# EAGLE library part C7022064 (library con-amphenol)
AMPHENOL CONNECTOR
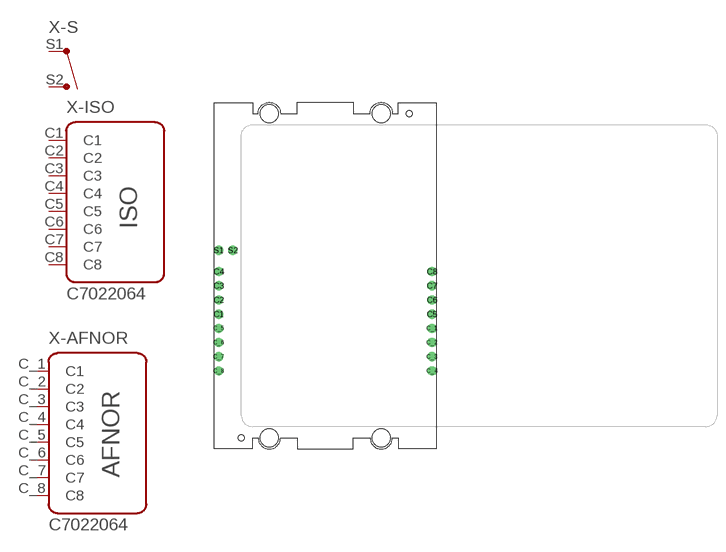
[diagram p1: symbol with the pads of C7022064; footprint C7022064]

Designator prefix X; gates -S=S -ISO=ISO8 -AFNOR=AFNOR

## C7022064 (OC_FARNELL: unknown; OC_NEWARK: unknown)  [C7022064]
C1  -ISO:C1  pas
C2  -ISO:C2  pas
C3  -ISO:C3  pas
C4  -ISO:C4  pas
C5  -ISO:C5  pas
C6  -ISO:C6  pas
C7  -ISO:C7  pas
C8  -ISO:C8  pas
C_1  -AFNOR:C1  pas
C_2  -AFNOR:C2  pas
C_3  -AFNOR:C3  pas
C_4  -AFNOR:C4  pas
C_5  -AFNOR:C5  pas
C_6  -AFNOR:C6  pas
C_7  -AFNOR:C7  pas
C_8  -AFNOR:C8  pas
S1  -S:S1  pas
S2  -S:S2  pas

## Footprint C7022064 (pad centres in mm)
AMPHENOL CONNECTOR
drill 1.1 round: C1 -19.05,-6.88; C2 -19.05,-4.34; C3 -19.05,-1.8; C4 -19.05,0.74; C5 19.05,-6.88; C6 19.05,-4.34; C7 19.05,-1.8; C8 19.05,0.74; C_1 19.05,-9.42; C_2 19.05,-11.96; C_3 19.05,-14.5; C_4 19.05,-17.04; C_5 -19.05,-9.42; C_6 -19.05,-11.96; C_7 -19.05,-14.5; C_8 -19.05,-17.04; S1 -19.05,4.55; S2 -16.51,4.55
hole 3.2 at -10,-29
hole 3.2 at 10,-29
hole 3.2 at 10,29
hole 3.2 at -10,29
hole 1.1 at -15,-29
hole 1.1 at 15,29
